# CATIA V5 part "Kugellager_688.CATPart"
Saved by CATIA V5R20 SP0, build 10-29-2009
Part number: Kugellager_688
Bounding box of the stored display mesh (mm): x -8 to 8, y -7.999 to 7.999, z -3 to 3
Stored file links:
  C:\Users\Andi\Desktop\Plasma\Kugellager_688.CATPart
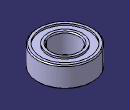
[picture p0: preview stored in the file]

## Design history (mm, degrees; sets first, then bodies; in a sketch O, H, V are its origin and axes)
AxisSystem1: origin (0, 0, 0), X (1, 0, 0), Y (0, 1, 0), Z (0, 0, 1)
Body1 (main body)
  Sketch1 on YZ plane of AxisSystem1, origin (0, 0, 0), H (0, 1, 0), V (0, 0, 1)
    line L1 (4, -3) -> (4, 3)
    line L2 (4, 3) -> (5, 3)
    line L3 (5, 3) -> (5, 2.5)
    line L4 (5, 2.5) -> (7, 2.5)
    line L5 (7, 2.5) -> (7, 3)
    point P6 (7, 3)
    line L6 (7, 3) -> (8, 3)
    line L7 (8, 3) -> (8, -3)
    line L8 (8, -3) -> (7, -3)
    point P9 (7, -3)
    line L9 (7, -3) -> (7, -2.5)
    line L10 (7, -2.5) -> (5, -2.5)
    point P11 (5, -2.5)
    line L11 (5, -2.5) -> (5, -3)
    point P12 (5, -3)
    line L12 (5, -3) -> (4, -3)
    reference projected line E1 through (0, 0) direction (0, 1) from edge [ZX plane of AxisSystem1 | YZ plane of AxisSystem1]
    construction line L13 (6, 2.5) -> (6, -2.5)
    point P13 (6, 2.5)
    point P14 (6, -2.5)
    distance L1 V = 4
    distance L7 E1 = 8
    length L7 = 6
    distance L4 L6 = 0.5
    distance L3 L1 = 1
    vertical: L1 V, L3 V, L5 V, L7 V, L9 V, L11 V, L13 V
    horizontal: L2 H, L4 H, L6 H, L8 H, L10 H, L12 H
    coincidence: P6 L2, P9 L5, P11 L3, P12 L8
    symmetry: L8 L6 H, L10 L4 H, L3 L5 L13, L1 L7 L13
    midpoint: P13 L4, P14 L10
  Shaft1: profile Sketch1, axis Sketch1.V, angle 360
  Chamfer1: length 0.3, angle 45, on edge [face of Shaft1 from Sketch1.L7 | face of Shaft1 from Sketch1.L6]; edge [face of Shaft1 from Sketch1.L8 | face of Shaft1 from Sketch1.L7]; edge [face of Shaft1 from Sketch1.L2 | face of Shaft1 from Sketch1.L1]; edge [face of Shaft1 from Sketch1.L1 | face of Shaft1 from Sketch1.L12]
